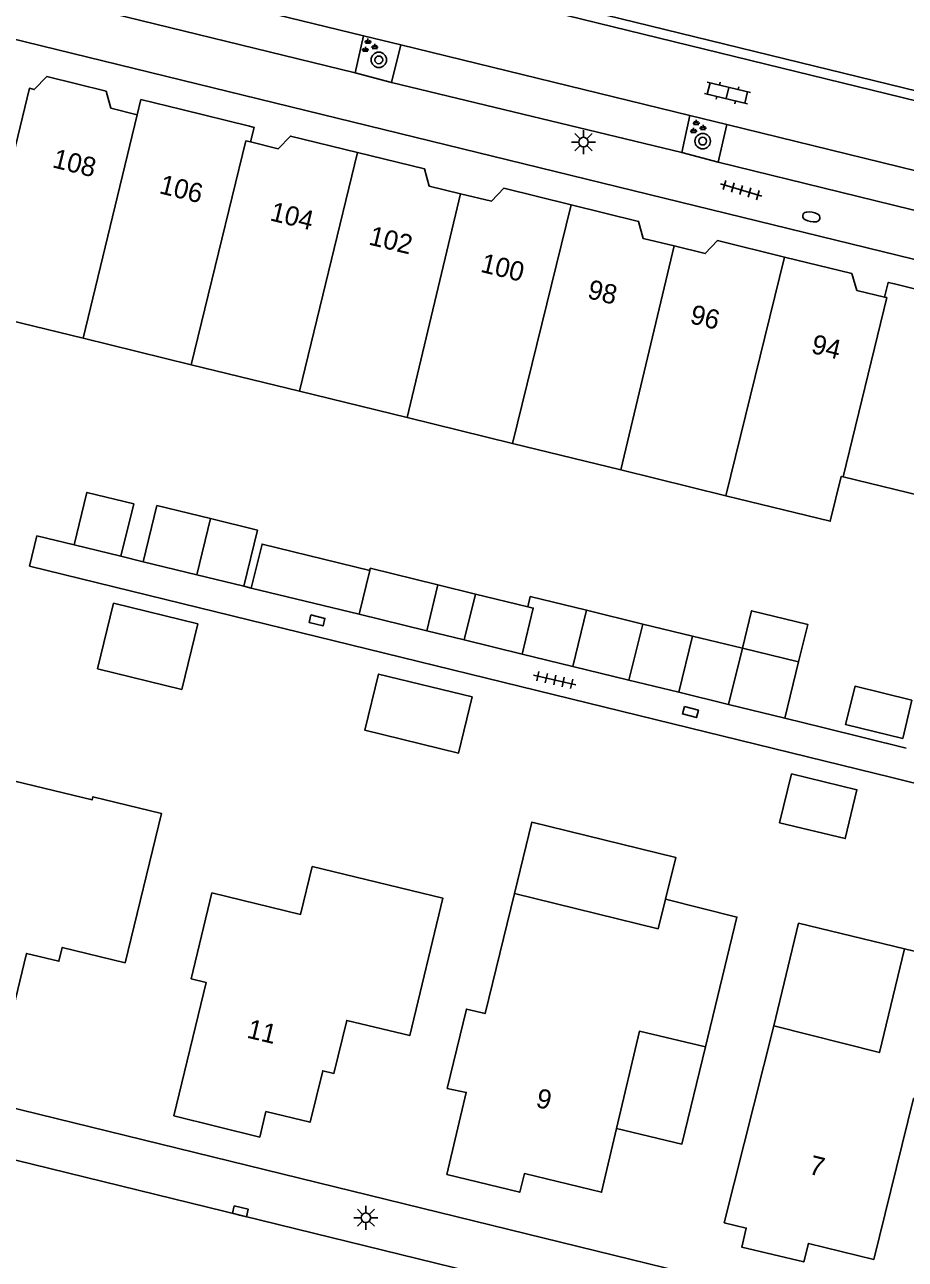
# Model space of a CAD drawing. Extents: x 125000 to 129004, y 397500 to 399008.
# Drawn here: x 126436.9 to 126482.6, y 398505.4 to 398569.4 of the extents above; entities that cross this region are included whole.
import ezdxf

# ---------------------------------------------------------------- set-up
doc = ezdxf.new("R2010")
doc.units = 0
for name, color, linetype in [('gg-afsc-erfafscheiding', 7, 'Continuous'), ('gg-afsc-hekwerk', 7, 'Continuous'), ('gg-anno-huisnummerreeks BGT', 7, 'Continuous'), ('gg-bbg-bijgebouw', 7, 'Continuous'), ('gg-bbg-gedigitaliseerde bebouwing', 7, 'Continuous'), ('gg-bbg-gedigitaliseerde bijgebouw', 7, 'Continuous'), ('gg-bbg-hoofdgebouw', 7, 'Continuous'), ('gg-bbg-luifel en loopbrug', 7, 'Continuous'), ('gg-bbg-tussenscheiding', 7, 'Continuous'), ('gg-knt-verharding', 7, 'Continuous'), ('gg-knt-verharding nz', 7, 'Continuous'), ('gt-symb-boom', 7, 'Continuous'), ('gt-symb-brandkraan', 7, 'Continuous'), ('gt-symb-groenvak', 7, 'Continuous'), ('gt-symb-klinker verharding', 7, 'Continuous'), ('gt-symb-kolk', 7, 'Continuous'), ('gt-symb-kolk center center', 7, 'Continuous'), ('gt-symb-lichtmast', 7, 'Continuous'), ('gt-symb-tegel verharding', 7, 'Continuous')]:
    doc.layers.add(name, color=color, linetype=linetype)

# ---------------------------------------------------------------- blocks, each defined once
blk = doc.blocks.new('gt0-BOOM')
at = {"layer": 'gt-symb-boom'}
for radius in [0.4, 0.2]:
    blk.add_circle((0, 0), radius, dxfattribs=at)
blk = doc.blocks.new('gt0-LMAST')
at = {"layer": 'gt-symb-lichtmast'}
for p, q in [((-0.182, 0.173), (-0.447, 0.438)), ((-0.005, 0.246), (-0.005, 0.621)), ((0.172, 0.173), (0.437, 0.438)), ((-0.255, -0.004), (-0.63, -0.004)), ((-0.182, -0.181), (-0.447, -0.446)), ((-0.005, -0.254), (-0.005, -0.629)), ((0.437, -0.446), (0.172, -0.181)), ((0.245, -0.004), (0.62, -0.004))]:
    blk.add_line(p, q, dxfattribs=at)
blk.add_circle((-0.005, -0.004), 0.25, dxfattribs=at)
blk = doc.blocks.new('gt0-GRVAK')
at = {"layer": 'gt-symb-groenvak'}
for p, q in [((-0.11, 0.189), (-0.228, 0.24)), ((-0.182, 0.153), (0.088, 0.153)), ((-0.091, 0.211), (-0.156, 0.322)), ((-0.047, 0.214), (-0.047, 0.393)), ((-0.004, 0.211), (0.061, 0.322)), ((0.015, 0.189), (0.133, 0.24)), ((0.262, -0.052), (0.197, 0.059)), ((0.305, -0.049), (0.305, 0.13)), ((0.349, -0.052), (0.414, 0.059)), ((-0.245, -0.228), (-0.363, -0.177)), ((-0.318, -0.264), (-0.047, -0.264)), ((-0.226, -0.206), (-0.291, -0.095)), ((-0.183, -0.203), (-0.183, -0.024)), ((-0.139, -0.206), (-0.074, -0.095)), ((-0.12, -0.228), (-0.002, -0.177)), ((0.243, -0.074), (0.125, -0.023)), ((0.17, -0.11), (0.441, -0.11)), ((0.368, -0.074), (0.486, -0.023))]:
    blk.add_line(p, q, dxfattribs=at)
blk = doc.blocks.new('gt0-BR')
at = {"layer": 'gt-symb-brandkraan'}
for centre, radius, start, end in [((-0.244, 0), 0.206, 107.56694, 252.43307), ((0.599, -2.664), 3, 106.89205, 107.56694), ((0, -0.691), 0.938, 73.10799, 106.89205), ((-0.599, -2.664), 3, 72.43309, 73.10799), ((0.244, 0), 0.206, 287.56695, 72.43309), ((0.599, 2.664), 3, 252.43307, 253.10797), ((0, 0.691), 0.938, 253.10797, 286.89206), ((-0.599, 2.664), 3, 286.89206, 287.56695)]:
    blk.add_arc(centre, radius, start, end, dxfattribs=at)
blk = doc.blocks.new('gt0-TEG1')
at = {"layer": 'gt-symb-tegel verharding'}
for p, q in [((-1.125, 0), (1.125, 0)), ((-0.9, -0.25), (-0.9, 0.25)), ((-0.45, -0.25), (-0.45, 0.25)), ((0, -0.25), (0, 0.25)), ((0.45, -0.25), (0.45, 0.25)), ((0.9, -0.25), (0.9, 0.25))]:
    blk.add_line(p, q, dxfattribs=at)
blk = doc.blocks.new('gt0-KL1')
at = {"layer": 'gt-symb-klinker verharding'}
for p, q in [((-1.15, 0.3), (1.15, 0.3)), ((-1, -0.3), (-1, 0.3)), ((-0.5, 0.3), (-0.5, 0.45)), ((0, -0.3), (0, 0.3)), ((0.5, 0.3), (0.5, 0.45)), ((1, -0.3), (1, 0.3)), ((-1.15, -0.3), (1.15, -0.3)), ((-0.5, -0.45), (-0.5, -0.3)), ((0.5, -0.45), (0.5, -0.3))]:
    blk.add_line(p, q, dxfattribs=at)
blk = doc.blocks.new('gt0-KOLKCC')
at = {"layer": 'gt-symb-kolk center center'}
blk.add_lwpolyline([(-0.375, 0.2), (0.375, 0.2), (0.375, -0.2), (-0.375, -0.2)], close=True, dxfattribs=at)
blk = doc.blocks.new('gt0-KOLK')
at = {"layer": 'gt-symb-kolk'}
blk.add_lwpolyline([(0, 0), (0.375, 0), (0.375, 0.4), (-0.375, 0.4), (-0.375, 0), (0, 0)], dxfattribs=at)

msp = doc.modelspace()

# ---------------------------------------------------------------- linework, layer by layer
at = {"layer": 'gg-afsc-erfafscheiding'}
for p, q in [((126437.563, 398542.893), (126437.17, 398541.314)), ((126439.491, 398542.423), (126437.563, 398542.893)), ((126443.077, 398541.55), (126441.92, 398541.832)), ((126437.17, 398541.314), (126481.914, 398530.358)), ((126448.679, 398540.185), (126448.29, 398540.28)), ((126476.358, 398533.44), (126478.328, 398532.955)), ((126478.328, 398532.955), (126482.654, 398531.879))]:
    msp.add_line(p, q, dxfattribs=at)
at = {"layer": 'gg-afsc-hekwerk'}
msp.add_line((126499.249, 398526.124), (126481.914, 398530.358), dxfattribs=at)
at = {"layer": 'gg-bbg-bijgebouw'}
msp.add_lwpolyline([(126482.469, 398532.382), (126482.943, 398534.368), (126480.004, 398535.094), (126479.512, 398533.104), (126482.469, 398532.382)], dxfattribs=at)
at = {"layer": 'gg-bbg-gedigitaliseerde bebouwing'}
for p, q in [((126439.953, 398553.137), (126434.359, 398554.507)), ((126445.565, 398551.763), (126439.953, 398553.137)), ((126451.174, 398550.39), (126445.565, 398551.763)), ((126456.762, 398549.022), (126451.174, 398550.39)), ((126462.231, 398547.683), (126456.762, 398549.022)), ((126467.848, 398546.307), (126462.231, 398547.683)), ((126473.291, 398544.975), (126467.848, 398546.307)), ((126485.164, 398544.534), (126479.383, 398545.949))]:
    msp.add_line(p, q, dxfattribs=at)
msp.add_lwpolyline([(126473.291, 398544.975), (126478.711, 398543.648), (126479.28, 398545.974), (126479.383, 398545.949)], dxfattribs=at)
at = {"layer": 'gg-bbg-gedigitaliseerde bijgebouw'}
for p, q in [((126446.571, 398543.786), (126445.861, 398540.871)), ((126441.92, 398541.832), (126439.491, 398542.423)), ((126448.29, 398540.28), (126445.861, 398540.871)), ((126458.364, 398540.349), (126457.782, 398537.967)), ((126454.269, 398538.823), (126448.679, 398540.185)), ((126459.727, 398537.493), (126460.307, 398539.874)), ((126460.307, 398539.874), (126463.026, 398539.212)), ((126465.358, 398536.121), (126466.07, 398539.033)), ((126466.07, 398539.033), (126468.984, 398538.321)), ((126457.782, 398537.967), (126454.269, 398538.823)), ((126468.984, 398538.321), (126468.273, 398535.41)), ((126462.727, 398536.762), (126459.727, 398537.493)), ((126474.156, 398537.067), (126473.443, 398534.15)), ((126477.07, 398536.354), (126474.156, 398537.067)), ((126468.273, 398535.41), (126465.358, 398536.121)), ((126476.358, 398533.44), (126477.07, 398536.354)), ((126476.358, 398533.44), (126473.443, 398534.15))]:
    msp.add_line(p, q, dxfattribs=at)
for points in [[(126441.92, 398541.832), (126442.583, 398544.552), (126440.154, 398545.144), (126439.491, 398542.423)], [(126448.29, 398540.28), (126449, 398543.194), (126446.571, 398543.786)], [(126448.679, 398540.185), (126449.237, 398542.467), (126454.826, 398541.101)], [(126454.826, 398541.101), (126454.852, 398541.208), (126458.364, 398540.349)], [(126463.026, 398539.212), (126463.307, 398539.143), (126462.727, 398536.762)], [(126476.694, 398530.547), (126480.097, 398529.726), (126479.487, 398527.198), (126476.085, 398528.019), (126476.694, 398530.547)]]:
    msp.add_lwpolyline(points, dxfattribs=at)
at = {"layer": 'gg-bbg-hoofdgebouw'}
for p, q in [((126487.624, 398554.598), (126482.046, 398555.955)), ((126487.589, 398520.262), (126482.558, 398521.476))]:
    msp.add_line(p, q, dxfattribs=at)
for points in [[(126442.766, 398564.73), (126441.396, 398565.064), (126441.148, 398565.947), (126438.076, 398566.71), (126437.426, 398566.034), (126437.175, 398566.105), (126434.359, 398554.507)], [(126448.591, 398564.133), (126445.073, 398565.001), (126442.957, 398565.517), (126442.766, 398564.73)], [(126448.638, 398563.318), (126448.825, 398564.075), (126448.591, 398564.133)], [(126454.196, 398562.77), (126450.72, 398563.618), (126450.075, 398562.964), (126448.638, 398563.318)], [(126459.525, 398560.635), (126457.915, 398561.018), (126457.672, 398561.921), (126454.196, 398562.77)], [(126465.275, 398560.059), (126461.78, 398560.918), (126461.135, 398560.252), (126459.525, 398560.635)], [(126470.62, 398557.924), (126469.007, 398558.317), (126468.769, 398559.199), (126465.275, 398560.059)], [(126476.342, 398557.348), (126472.857, 398558.201), (126472.232, 398557.53), (126470.62, 398557.924)], [(126481.531, 398555.273), (126480.098, 398555.621), (126479.826, 398556.495), (126476.342, 398557.348)], [(126482.046, 398555.955), (126481.717, 398556.035), (126481.531, 398555.273)], [(126428.866, 398518.12), (126432.474, 398517.239), (126432.267, 398516.393), (126435.642, 398515.569), (126437.026, 398521.239), (126438.699, 398520.831), (126438.874, 398521.55), (126442.132, 398520.755), (126444.02, 398528.496), (126440.464, 398529.364), (126440.424, 398529.199), (126436.416, 398530.172), (126435.982, 398528.382), (126431.634, 398529.437), (126428.866, 398518.12)], [(126444.663, 398512.819), (126449.124, 398511.714), (126449.439, 398513.034), (126451.728, 398512.488), (126452.387, 398515.155), (126452.97, 398515.015), (126453.631, 398517.765), (126456.901, 398516.98), (126458.625, 398524.103), (126451.841, 398525.745), (126451.24, 398523.264), (126446.637, 398524.378), (126445.558, 398519.928), (126446.336, 398519.739), (126444.663, 398512.819)], [(126462.327, 398524.345), (126460.808, 398518.119), (126459.836, 398518.354), (126458.842, 398514.239), (126459.831, 398514.028), (126458.827, 398509.767)], [(126470.168, 398524.053), (126469.785, 398522.52), (126462.327, 398524.345)], [(126472.238, 398516.399), (126473.875, 398523.126), (126470.168, 398524.053)], [(126482.558, 398521.476), (126481.26, 398516.101), (126475.782, 398517.478)], [(126475.782, 398517.478), (126473.218, 398507.277), (126474.359, 398506.995), (126474.123, 398506.013), (126477.334, 398505.242), (126477.578, 398506.199), (126480.968, 398505.374), (126483.031, 398513.722), (126485.829, 398513.111), (126487.589, 398520.262)], [(126467.628, 398512.166), (126468.811, 398517.204), (126472.238, 398516.399)], [(126458.827, 398509.767), (126462.61, 398508.851), (126462.848, 398509.82), (126466.851, 398508.856), (126467.628, 398512.166)]]:
    msp.add_lwpolyline(points, dxfattribs=at)
at = {"layer": 'gg-bbg-luifel en loopbrug'}
for p, q in [((126445.861, 398540.871), (126443.077, 398541.55)), ((126460.307, 398539.874), (126458.364, 398540.349)), ((126468.984, 398538.321), (126471.57, 398537.694)), ((126459.727, 398537.493), (126457.782, 398537.967)), ((126471.57, 398537.694), (126470.858, 398534.78)), ((126471.57, 398537.694), (126474.156, 398537.067)), ((126465.358, 398536.121), (126462.727, 398536.762)), ((126470.858, 398534.78), (126468.273, 398535.41)), ((126473.443, 398534.15), (126470.858, 398534.78))]:
    msp.add_line(p, q, dxfattribs=at)
for points in [[(126446.571, 398543.786), (126443.787, 398544.464), (126443.077, 398541.55)], [(126466.07, 398539.033), (126463.155, 398539.743), (126463.026, 398539.212)], [(126445.906, 398538.329), (126445.076, 398534.929), (126440.705, 398535.997), (126441.535, 398539.397), (126445.906, 398538.329)], [(126474.156, 398537.067), (126474.628, 398539.01), (126477.543, 398538.303), (126477.07, 398536.354)], [(126460.144, 398534.541), (126459.433, 398531.626), (126454.575, 398532.812), (126455.287, 398535.727), (126460.144, 398534.541)], [(126462.327, 398524.345), (126463.228, 398528.037), (126470.695, 398526.213), (126470.168, 398524.053)], [(126482.558, 398521.476), (126477.066, 398522.801), (126475.782, 398517.478)], [(126467.628, 398512.166), (126471.019, 398511.348), (126472.238, 398516.399)]]:
    msp.add_lwpolyline(points, dxfattribs=at)
at = {"layer": 'gg-bbg-tussenscheiding'}
for p, q in [((126439.953, 398553.137), (126442.766, 398564.73)), ((126451.174, 398550.39), (126454.196, 398562.77)), ((126456.762, 398549.022), (126459.525, 398560.635)), ((126462.231, 398547.683), (126465.275, 398560.059)), ((126467.848, 398546.307), (126470.62, 398557.924)), ((126476.342, 398557.348), (126473.291, 398544.975)), ((126454.826, 398541.101), (126454.269, 398538.823))]:
    msp.add_line(p, q, dxfattribs=at)
for points in [[(126445.565, 398551.763), (126448.406, 398563.375), (126448.638, 398563.318)], [(126479.383, 398545.949), (126481.644, 398555.246), (126481.531, 398555.273)]]:
    msp.add_lwpolyline(points, dxfattribs=at)
at = {"layer": 'gg-knt-verharding'}
for p, q in [((126513.861, 398558.458), (126401.799, 398585.868)), ((126513.742, 398557.972), (126406.588, 398584.182)), ((126454.51, 398568.819), (126454.065, 398566.907)), ((126456.444, 398568.353), (126454.51, 398568.819)), ((126455.959, 398566.4), (126456.444, 398568.353)), ((126454.065, 398566.907), (126455.959, 398566.4)), ((126471.021, 398562.763), (126455.959, 398566.4)), ((126471.423, 398564.681), (126471.021, 398562.763)), ((126473.352, 398564.22), (126471.423, 398564.681)), ((126472.891, 398562.278), (126473.352, 398564.22)), ((126471.021, 398562.763), (126472.891, 398562.278))]:
    msp.add_line(p, q, dxfattribs=at)
for points in [[(126488.681, 398555.856), (126399.754, 398577.627), (126399.403, 398576.2)], [(126454.065, 398566.907), (126438.487, 398570.714), (126438.905, 398572.629)], [(126495.165, 398558.867), (126494.68, 398556.931), (126472.891, 398562.278)], [(126534.627, 398482.986), (126524.37, 398491.638), (126387.926, 398525.085), (126386.968, 398525.335)]]:
    msp.add_lwpolyline(points, dxfattribs=at)
at = {"layer": 'gg-knt-verharding nz'}
for p, q in [((126438.905, 398572.629), (126454.51, 398568.819)), ((126471.423, 398564.681), (126456.444, 398568.353)), ((126495.165, 398558.867), (126473.352, 398564.22))]:
    msp.add_line(p, q, dxfattribs=at)
msp.add_lwpolyline([(126388.129, 398522.392), (126405.708, 398518.092), (126433.707, 398511.188), (126463.681, 398503.845), (126479.173, 398500.034), (126522.795, 398489.385)], dxfattribs=at)

# ---------------------------------------------------------------- block references
at = {"layer": 'gt-symb-boom'}
for p in [(126455.297, 398567.575), (126472.096, 398563.36)]:
    msp.add_blockref('gt0-BOOM', p, dxfattribs=at)
at = {"layer": 'gt-symb-brandkraan', "rotation": 170.0949207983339}
msp.add_blockref('gt0-BR', (126477.73, 398559.43), dxfattribs=at)
at = {"layer": 'gt-symb-groenvak'}
for p in [(126454.781, 398568.282), (126471.807, 398564.077)]:
    msp.add_blockref('gt0-GRVAK', p, dxfattribs=at)
at = {"layer": 'gt-symb-klinker verharding', "rotation": -13.591560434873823}
msp.add_blockref('gt0-KL1', (126473.379, 398565.857), dxfattribs=at)
at = {"layer": 'gt-symb-kolk', "rotation": -13.772145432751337}
msp.add_blockref('gt0-KOLK', (126448.065, 398507.672), dxfattribs=at)
at = {"layer": 'gt-symb-kolk center center'}
for p, rotation in [((126452.091, 398538.507), -14.481034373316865), ((126471.459, 398533.753), -14.647375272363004)]:
    msp.add_blockref('gt0-KOLKCC', p, dxfattribs=dict(at, rotation=rotation))
at = {"layer": 'gt-symb-lichtmast'}
for p in [(126465.919, 398563.312), (126454.629, 398507.534)]:
    msp.add_blockref('gt0-LMAST', p, dxfattribs=at)
at = {"layer": 'gt-symb-tegel verharding'}
for p, rotation in [((126474.093, 398560.825), 163.14160123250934), ((126464.423, 398535.417), -13.119144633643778)]:
    msp.add_blockref('gt0-TEG1', p, dxfattribs=dict(at, rotation=rotation))

# ---------------------------------------------------------------- texts
at = {"layer": 'gg-anno-huisnummerreeks BGT'}
for s, rotation, p in [('108', 346.1, (126438.314, 398562.014)), ('106', 346.1, (126443.856, 398560.668)), ('104', 346.3, (126449.601, 398559.259)), ('102', 346.3, (126454.726, 398558.007)), ('100', 346.2, (126460.522, 398556.592)), ('98', 346.2, (126466.068, 398555.228)), ('96', 346.2, (126471.386, 398553.928)), ('94', 346.2, (126477.673, 398552.389)), ('11', 346.6, (126448.406, 398516.879)), ('9', 346.5, (126463.394, 398513.289)), ('7', 346.2, (126477.551, 398509.817))]:
    msp.add_text(s, height=1, rotation=rotation, dxfattribs=at).set_placement(p)

doc.saveas('drawing.dxf')
